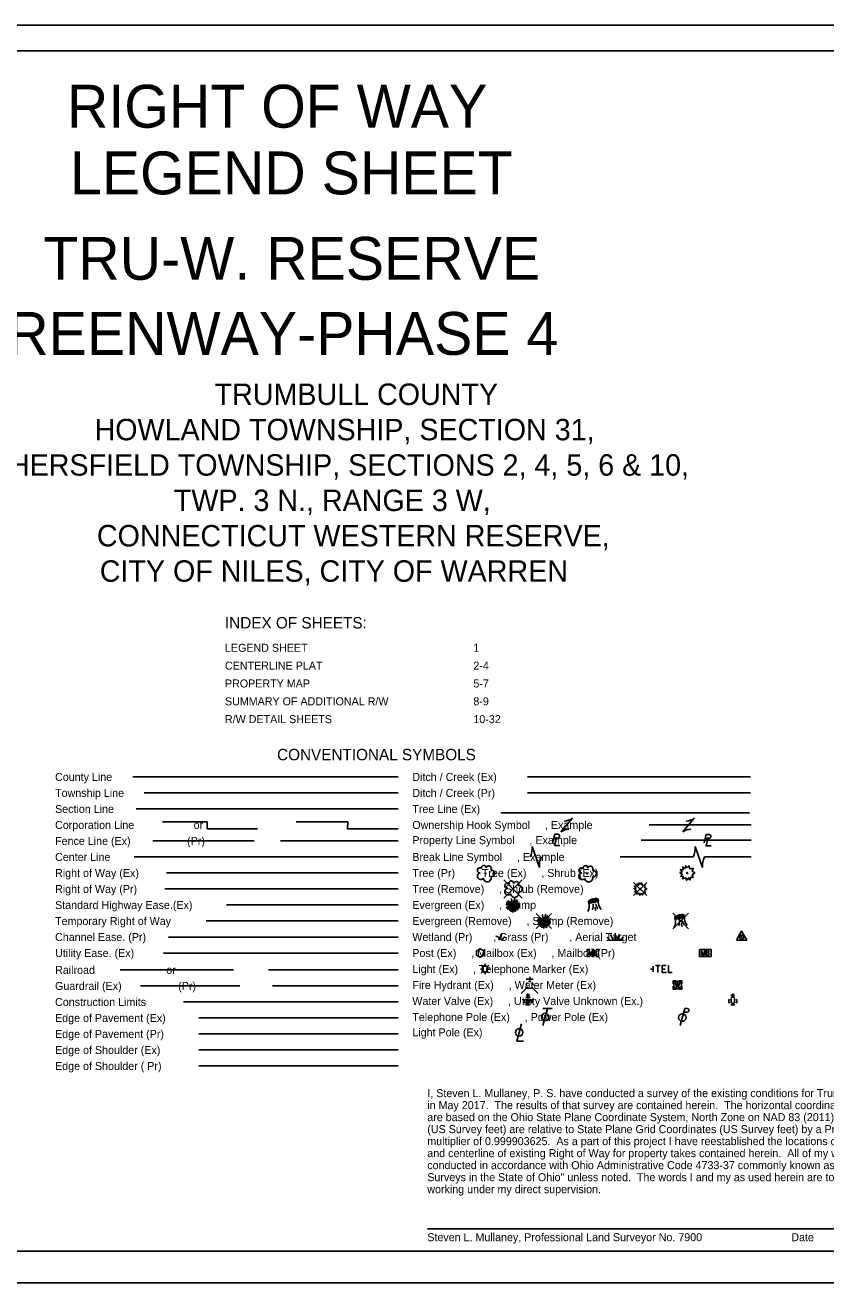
# Model space of a CAD drawing. Extents: x 0 to 34, y -0.1 to 32.4.
# Drawn here: x 11.7 to 25.7, y -0.05 to 21.95 of the extents above; entities that cross this region are included whole.
import ezdxf

# ---------------------------------------------------------------- set-up
doc = ezdxf.new("R2010")
doc.units = 0
for name, color, linetype in [('SH_Border', 7, 'Continuous'), ('SH_Data', 7, 'Continuous'), ('TX_P_Misc', 7, 'Continuous')]:
    doc.layers.add(name, color=color, linetype=linetype)

msp = doc.modelspace()

# ---------------------------------------------------------------- linework, layer by layer
at = {"layer": 'SH_Border'}
msp.add_lwpolyline([(0.001, -0.053), (34.001, -0.053), (34.001, 21.947), (0.001, 21.947)], close=True, dxfattribs=at)
at = {"layer": 'SH_Data'}
msp.add_lwpolyline([(2, 21.5), (33.5, 21.5), (33.5, 0.5), (2, 0.5)], close=True, dxfattribs=at)
at = {"layer": 'TX_P_Misc'}
for p, q in [((13.581, 8.797), (18.22, 8.797)), ((20.486, 8.797), (24.386, 8.797)), ((13.779, 8.517), (18.22, 8.517)), ((20.486, 8.517), (24.386, 8.517)), ((13.636, 8.237), (18.22, 8.237)), ((20.018, 8.167), (24.368, 8.167)), ((14.1, 8.013), (14.883, 8.013)), ((14.883, 8.013), (14.883, 7.887)), ((21.07, 7.834), (21.27, 8.074)), ((21.17, 7.954), (21.17, 7.954)), ((22.616, 7.957), (24.398, 7.957)), ((23.202, 7.834), (23.402, 8.074)), ((23.302, 7.954), (23.302, 7.954)), ((14.883, 7.887), (15.764, 7.887)), ((20.946, 7.726), (21.011, 7.726)), ((23.595, 7.722), (23.66, 7.722)), ((13.933, 7.677), (15.706, 7.677)), ((16.163, 7.677), (18.22, 7.677)), ((20.564, 7.581), (20.694, 7.213)), ((20.987, 7.695), (20.987, 7.695)), ((22.475, 7.692), (24.398, 7.692)), ((23.416, 7.581), (23.546, 7.213)), ((23.635, 7.691), (23.635, 7.691)), ((13.601, 7.397), (18.22, 7.397)), ((20.629, 7.397), (20.629, 7.397)), ((22.105, 7.397), (23.381, 7.397)), ((23.481, 7.397), (23.481, 7.397)), ((23.581, 7.397), (24.398, 7.397)), ((14.169, 7.117), (18.22, 7.117)), ((14.141, 6.837), (18.22, 6.837)), ((20.071, 6.997), (20.392, 6.676)), ((20.392, 6.997), (20.071, 6.676)), ((20.232, 6.837), (20.232, 6.837)), ((22.342, 6.953), (22.574, 6.721)), ((22.574, 6.953), (22.342, 6.721)), ((22.458, 6.837), (22.458, 6.837)), ((20.23, 6.557), (20.132, 6.614)), ((20.23, 6.557), (20.142, 6.644)), ((20.23, 6.557), (20.199, 6.672)), ((20.23, 6.557), (20.261, 6.674)), ((20.23, 6.557), (20.296, 6.654)), ((20.23, 6.557), (20.321, 6.627)), ((15.22, 6.557), (18.22, 6.557)), ((20.106, 6.557), (20.23, 6.557)), ((20.23, 6.557), (20.119, 6.586)), ((20.23, 6.557), (20.122, 6.518)), ((20.23, 6.557), (20.13, 6.5)), ((20.23, 6.557), (20.132, 6.482)), ((20.23, 6.557), (20.156, 6.47)), ((20.23, 6.557), (20.172, 6.456)), ((20.23, 6.557), (20.188, 6.448)), ((20.23, 6.557), (20.198, 6.435)), ((20.23, 6.557), (20.216, 6.442)), ((20.23, 6.557), (20.348, 6.597)), ((20.23, 6.557), (20.342, 6.559)), ((20.23, 6.426), (20.23, 6.557)), ((20.23, 6.557), (20.253, 6.441)), ((20.23, 6.557), (20.278, 6.44)), ((20.23, 6.557), (20.293, 6.462)), ((20.23, 6.557), (20.319, 6.469)), ((20.23, 6.557), (20.325, 6.493)), ((20.23, 6.557), (20.341, 6.508)), ((20.23, 6.557), (20.35, 6.533)), ((20.639, 6.41), (20.906, 6.143)), ((20.906, 6.41), (20.639, 6.143)), ((20.772, 6.277), (20.741, 6.392)), ((20.772, 6.277), (20.804, 6.394)), ((21.658, 6.557), (21.658, 6.557)), ((23.026, 6.416), (23.304, 6.138)), ((23.304, 6.416), (23.026, 6.138)), ((14.865, 6.277), (18.22, 6.277)), ((20.649, 6.277), (20.772, 6.277)), ((20.772, 6.277), (20.662, 6.306)), ((20.772, 6.277), (20.665, 6.238)), ((20.772, 6.277), (20.673, 6.22)), ((20.772, 6.277), (20.675, 6.334)), ((20.772, 6.277), (20.675, 6.202)), ((20.772, 6.277), (20.685, 6.364)), ((20.772, 6.277), (20.699, 6.19)), ((20.772, 6.277), (20.714, 6.176)), ((20.772, 6.277), (20.731, 6.168)), ((20.772, 6.277), (20.741, 6.155)), ((20.772, 6.277), (20.759, 6.162)), ((20.772, 6.277), (20.839, 6.374)), ((20.772, 6.277), (20.864, 6.347)), ((20.772, 6.277), (20.891, 6.317)), ((20.772, 6.277), (20.885, 6.279)), ((20.772, 6.146), (20.772, 6.277)), ((20.772, 6.277), (20.795, 6.161)), ((20.772, 6.277), (20.821, 6.16)), ((20.772, 6.277), (20.836, 6.182)), ((20.772, 6.277), (20.862, 6.189)), ((20.772, 6.277), (20.868, 6.213)), ((20.772, 6.277), (20.884, 6.228)), ((20.772, 6.277), (20.893, 6.253)), ((20.772, 6.277), (20.772, 6.277)), ((23.165, 6.277), (23.165, 6.277)), ((23.165, 6.277), (23.165, 6.277)), ((14.202, 5.997), (18.22, 5.997)), ((21.939, 5.936), (21.871, 5.993)), ((21.988, 5.936), (21.935, 6.043)), ((22.018, 5.937), (22.016, 6.062)), ((22.048, 5.937), (22.097, 6.045)), ((22.096, 5.938), (22.163, 5.997)), ((21.604, 5.778), (21.654, 5.778)), ((21.871, 5.935), (22.164, 5.939)), ((14.119, 5.717), (18.22, 5.717)), ((19.696, 5.485), (19.677, 5.504)), ((19.744, 5.501), (19.744, 5.527)), ((19.811, 5.504), (19.792, 5.485)), ((21.604, 5.656), (21.654, 5.656)), ((21.629, 5.717), (21.629, 5.717)), ((23.596, 5.717), (23.596, 5.717)), ((13.358, 5.421), (15.344, 5.421)), ((15.953, 5.421), (18.22, 5.421)), ((19.692, 5.437), (19.665, 5.437)), ((19.696, 5.388), (19.677, 5.37)), ((19.744, 5.437), (19.744, 5.437)), ((19.744, 5.373), (19.744, 5.346)), ((19.811, 5.37), (19.792, 5.388)), ((19.823, 5.437), (19.796, 5.437)), ((20.523, 5.217), (20.523, 5.303)), ((22.685, 5.437), (22.635, 5.437)), ((22.685, 5.387), (22.685, 5.487)), ((13.712, 5.141), (15.455, 5.141)), ((16.024, 5.141), (18.22, 5.141)), ((20.481, 5.114), (20.377, 5.011)), ((20.583, 5.26), (20.463, 5.26)), ((20.523, 5.157), (20.523, 5.157)), ((20.523, 5.157), (20.523, 5.157)), ((20.565, 5.114), (20.669, 5.011)), ((23.11, 5.157), (23.11, 5.157)), ((14.464, 4.861), (18.22, 4.861)), ((20.524, 4.979), (20.46, 4.979)), ((20.492, 4.947), (20.492, 5.01)), ((20.492, 4.877), (20.492, 4.877)), ((24.109, 4.979), (24.045, 4.979)), ((24.05, 4.92), (24.05, 4.851)), ((24.077, 4.947), (24.077, 5.01)), ((24.077, 4.877), (24.077, 4.877)), ((24.104, 4.92), (24.104, 4.851)), ((20.836, 4.747), (20.755, 4.447)), ((20.916, 4.747), (20.756, 4.747)), ((23.237, 4.747), (23.157, 4.447)), ((23.22, 4.683), (23.279, 4.683)), ((23.237, 4.747), (23.279, 4.747)), ((14.736, 4.581), (18.22, 4.581)), ((14.736, 4.301), (18.22, 4.301)), ((14.736, 4.021), (18.22, 4.021)), ((14.736, 3.741), (18.22, 3.741)), ((18.737, 0.89), (29.675, 0.89))]:
    msp.add_line(p, q, dxfattribs=at)
for points in [[(16.436, 8.013), (17.34, 8.013), (17.334, 7.887), (18.22, 7.887)], [(20.925, 7.646), (20.965, 7.795), (21.016, 7.794)], [(21, 7.743), (20.96, 7.595), (21.048, 7.595)], [(23.574, 7.642), (23.613, 7.791), (23.665, 7.791)], [(23.648, 7.739), (23.609, 7.591), (23.696, 7.591)], [(23.275, 7.207), (23.305, 7.244), (23.326, 7.191), (23.381, 7.2), (23.364, 7.15), (23.411, 7.12), (23.368, 7.083), (23.381, 7.038), (23.343, 7.041), (23.327, 6.995), (23.305, 7.03), (23.271, 6.989), (23.25, 7.034), (23.199, 7.012), (23.208, 7.059), (23.168, 7.055), (23.192, 7.094), (23.153, 7.123), (23.19, 7.136), (23.16, 7.176), (23.206, 7.171), (23.205, 7.223), (23.242, 7.194), (23.253, 7.243), (23.275, 7.207)], [(22.454, 6.914), (22.48, 6.945), (22.498, 6.9), (22.544, 6.908), (22.53, 6.865), (22.57, 6.84), (22.534, 6.808), (22.544, 6.77), (22.512, 6.772), (22.498, 6.734), (22.48, 6.763), (22.451, 6.728), (22.433, 6.766), (22.39, 6.748), (22.398, 6.788), (22.363, 6.784), (22.384, 6.818), (22.351, 6.842), (22.382, 6.853), (22.357, 6.887), (22.396, 6.883), (22.395, 6.927), (22.427, 6.903), (22.436, 6.944), (22.454, 6.914)], [(19.591, 5.679), (19.656, 5.642), (19.721, 5.679), (19.721, 5.754), (19.656, 5.792), (19.591, 5.754), (19.591, 5.679)], [(21.529, 5.729), (21.529, 5.778), (21.578, 5.778)], [(21.564, 5.677), (21.564, 5.757), (21.593, 5.677), (21.621, 5.757), (21.621, 5.677)], [(21.68, 5.72), (21.683, 5.723), (21.685, 5.725), (21.687, 5.727), (21.687, 5.729), (21.689, 5.731), (21.689, 5.733), (21.69, 5.737), (21.69, 5.739), (21.69, 5.742), (21.69, 5.746), (21.689, 5.749), (21.687, 5.751), (21.683, 5.754), (21.681, 5.755), (21.68, 5.756), (21.677, 5.757), (21.646, 5.757), (21.646, 5.677), (21.68, 5.677), (21.685, 5.679), (21.689, 5.683), (21.692, 5.688), (21.694, 5.693), (21.694, 5.699), (21.694, 5.703), (21.693, 5.706), (21.69, 5.712), (21.687, 5.716), (21.68, 5.72), (21.646, 5.72)], [(21.68, 5.778), (21.729, 5.778), (21.729, 5.729)], [(23.531, 5.677), (23.531, 5.757), (23.56, 5.677), (23.588, 5.757), (23.588, 5.677)], [(23.647, 5.72), (23.65, 5.723), (23.652, 5.725), (23.654, 5.727), (23.654, 5.729), (23.655, 5.731), (23.656, 5.733), (23.657, 5.737), (23.657, 5.739), (23.657, 5.742), (23.657, 5.746), (23.655, 5.749), (23.654, 5.751), (23.65, 5.754), (23.648, 5.755), (23.647, 5.756), (23.644, 5.757), (23.613, 5.757), (23.613, 5.677), (23.647, 5.677), (23.652, 5.679), (23.655, 5.683), (23.659, 5.688), (23.661, 5.693), (23.661, 5.699), (23.661, 5.703), (23.66, 5.706), (23.657, 5.712), (23.654, 5.716), (23.647, 5.72), (23.613, 5.72)], [(21.578, 5.656), (21.529, 5.656), (21.529, 5.704)], [(21.729, 5.704), (21.729, 5.656), (21.68, 5.656)], [(22.726, 5.499), (22.804, 5.499)], [(22.765, 5.499), (22.765, 5.374)], [(22.911, 5.499), (22.843, 5.499), (22.843, 5.374), (22.916, 5.374)], [(22.843, 5.437), (22.891, 5.437)], [(22.95, 5.499), (22.95, 5.374), (23.018, 5.374)], [(23.09, 5.232), (23.035, 5.232), (23.035, 5.177)], [(23.035, 5.137), (23.035, 5.082), (23.09, 5.082)], [(23.077, 5.202), (23.094, 5.112), (23.11, 5.202), (23.127, 5.112), (23.144, 5.202)], [(23.185, 5.177), (23.185, 5.232), (23.13, 5.232)], [(23.13, 5.082), (23.185, 5.082), (23.185, 5.137)], [(20.46, 4.918), (20.476, 4.832), (20.492, 4.918), (20.508, 4.832), (20.524, 4.918)], [(20.378, 4.476), (20.299, 4.176), (20.417, 4.176)]]:
    msp.add_lwpolyline(points, dxfattribs=at)
for points in [[(24.141, 5.939), (24.321, 5.939), (24.231, 6.1)], [(23.496, 5.778), (23.696, 5.778), (23.696, 5.656), (23.496, 5.656)], [(19.711, 5.387), (19.777, 5.387), (19.777, 5.487), (19.711, 5.487)]]:
    msp.add_lwpolyline(points, close=True, dxfattribs=at)
for centre, radius in [((19.751, 7.109), 0.0084), ((21.528, 7.105), 0.0072), ((23.279, 7.117), 0.0115), ((20.232, 6.837), 0.0072), ((22.458, 6.837), 0.00979), ((24.231, 5.997), 0.035), ((24.231, 5.997), 0.008), ((23.11, 5.157), 0.0675), ((20.796, 4.597), 0.065), ((23.194, 4.587), 0.065), ((20.338, 4.328), 0.065)]:
    msp.add_circle(centre, radius, dxfattribs=at)
for centre, radius, start, end in [((21.112, 8.289), 0.267, 273.6945, 306.337), ((23.244, 8.289), 0.267, 273.6945, 306.337), ((21.011, 7.76), 0.0345, 270.471, 81.3281), ((21.228, 7.619), 0.267, 93.6945, 126.337), ((23.36, 7.619), 0.267, 93.6945, 126.337), ((23.659, 7.756), 0.0345, 270.471, 81.3281), ((20.232, 7.549), 0.334, 332.9422, 5.5848), ((23.084, 7.548), 0.334, 332.9422, 5.5848), ((21.026, 7.245), 0.334, 152.9422, 185.5848), ((23.878, 7.245), 0.334, 152.9422, 185.5848), ((19.666, 7.062), 0.0592, 96.1722, 320.5737), ((19.652, 7.165), 0.0441, 39.0625, 279.5412), ((19.722, 7.21), 0.0395, 354.0047, 205.9741), ((19.78, 7.031), 0.0685, 184.9476, 19.4572), ((19.806, 7.194), 0.0466, 323.83, 165.0376), ((19.855, 7.11), 0.0574, 259.1453, 101.4596), ((21.443, 7.059), 0.0592, 96.1722, 320.5737), ((21.429, 7.161), 0.0441, 39.0625, 279.5412), ((21.499, 7.206), 0.0395, 354.0047, 205.9741), ((21.557, 7.027), 0.0685, 184.9476, 19.4572), ((21.583, 7.19), 0.0466, 323.83, 165.0376), ((21.632, 7.106), 0.0574, 259.1453, 101.4596), ((20.146, 6.79), 0.0592, 96.1722, 320.5737), ((20.132, 6.893), 0.0441, 39.0625, 279.5412), ((20.202, 6.938), 0.0395, 354.0047, 205.9741), ((20.287, 6.922), 0.0466, 323.83, 165.0376), ((20.336, 6.838), 0.0574, 259.1453, 101.4596), ((20.26, 6.759), 0.0685, 184.9476, 19.4572), ((21.366, 6.54), 0.2, 331.5338, 20.9269), ((21.938, 6.614), 0.215, 171.4106, 219.9194), ((21.382, 6.558), 0.253, 340.7938, 3.5481), ((21.853, 6.517), 0.182, 178.7926, 197.1224), ((21.983, 6.66), 0.316, 194.9653, 212.1216), ((22.874, 6.26), 0.2, 331.5338, 20.9269), ((22.89, 6.278), 0.253, 340.7938, 3.5481), ((23.361, 6.237), 0.182, 178.7926, 197.1224), ((23.491, 6.38), 0.316, 194.9653, 212.1216), ((23.446, 6.334), 0.215, 171.4106, 219.9194), ((20.523, 5.157), 0.06, 140.021, 184.0629), ((20.523, 5.157), 0.06, 211.8788, 255.8479), ((20.523, 5.157), 0.06, 68.1395, 112.038), ((20.523, 5.157), 0.06, 283.8239, 329.9097), ((20.523, 5.157), 0.06, 356.0165, 39.9889), ((20.492, 4.877), 0.07, 150.0184, 209.9816), ((20.492, 4.877), 0.07, 60.0184, 120.0157), ((20.492, 4.877), 0.07, 330.0184, 29.9816), ((24.077, 4.877), 0.07, 150.0184, 209.9816), ((24.077, 4.877), 0.07, 60.0184, 120.0157), ((24.077, 4.864), 0.03, 205.1924, 334.8076), ((24.077, 4.877), 0.07, 330.0184, 29.9816), ((20.492, 4.877), 0.07, 239.9843, 299.9816), ((23.28, 4.715), 0.0319, 268.8767, 91.1233), ((24.077, 4.877), 0.07, 239.9843, 299.9816)]:
    msp.add_arc(centre, radius, start, end, dxfattribs=at)
for centre, major_axis in [((21.639, 6.632), (0.0868, 0.0187)), ((21.639, 6.632), (0.0651, 0.0141)), ((21.639, 6.632), (0.0488, 0.0105)), ((21.639, 6.632), (0.0275, 0.0059)), ((21.639, 6.632), (0.0154, 0.0033)), ((23.147, 6.352), (0.0868, 0.0187)), ((23.147, 6.352), (0.0651, 0.0141)), ((23.147, 6.352), (0.0488, 0.0105)), ((23.147, 6.352), (0.0275, 0.0059)), ((23.147, 6.352), (0.0154, 0.0033))]:
    msp.add_ellipse(centre, major_axis=major_axis, ratio=0.36865, dxfattribs=at)
for points in [[(19.933, 6.012), (19.975, 5.995), (19.992, 5.941)], [(20.021, 5.945), (20.021, 5.993), (20.026, 6.037), (20.035, 6.058)], [(20.048, 5.938), (20.06, 5.977), (20.09, 6)]]:
    msp.add_spline(points, degree=3, dxfattribs=at)

# ---------------------------------------------------------------- texts
for s, height, p in [('RIGHT OF WAY', 0.75, (12.427, 20.154)), ('LEGEND SHEET', 0.75, (12.48, 18.988)), ('TRU-W. RESERVE', 0.75, (12.014, 17.493)), ('GREENWAY-PHASE 4', 0.75, (10.603, 16.18)), ('TRUMBULL COUNTY', 0.375, (15.011, 15.304)), ('HOWLAND TOWNSHIP, SECTION 31,', 0.375, (12.91, 14.686)), ('WEATHERSFIELD TOWNSHIP, SECTIONS 2, 4, 5, 6 & 10,', 0.375, (9.964, 14.067)), ('TWP. 3 N., RANGE 3 W,', 0.375, (14.298, 13.448)), ('CONNECTICUT WESTERN RESERVE,', 0.375, (12.952, 12.829)), ('CITY OF NILES, CITY OF WARREN', 0.375, (13.002, 12.211)), ('INDEX OF SHEETS:', 0.2, (15.192, 11.394)), ('LEGEND SHEET', 0.14, (15.192, 10.986)), ('1', 0.14, (19.538, 10.986)), ('CENTERLINE PLAT', 0.14, (15.192, 10.674)), ('2-4', 0.14, (19.538, 10.674)), ('PROPERTY MAP', 0.14, (15.192, 10.362)), ('5-7', 0.14, (19.538, 10.362)), ('SUMMARY OF ADDITIONAL R/W', 0.14, (15.192, 10.05)), ('8-9', 0.14, (19.538, 10.05)), ('R/W DETAIL SHEETS', 0.14, (15.192, 9.738)), ('10-32', 0.14, (19.538, 9.738)), ('CONVENTIONAL SYMBOLS', 0.2, (16.104, 9.088)), ('County Line', 0.14, (12.22, 8.727)), ('Ditch / Creek (Ex)', 0.14, (18.47, 8.727)), ('Township Line', 0.14, (12.22, 8.447)), ('Ditch / Creek (Pr)', 0.14, (18.47, 8.447)), ('Section Line', 0.14, (12.22, 8.167)), ('Tree Line (Ex)', 0.14, (18.47, 8.167)), ('Corporation Line                    or', 0.14, (12.22, 7.887)), ('Ownership Hook Symbol     , Example', 0.14, (18.47, 7.887)), ('Fence Line (Ex)                   (Pr)', 0.14, (12.22, 7.607)), ('Property Line Symbol     , Example', 0.14, (18.47, 7.622)), ('Center Line', 0.14, (12.22, 7.327)), ('Break Line Symbol     , Example', 0.14, (18.47, 7.327)), ('Right of Way (Ex)', 0.14, (12.22, 7.047)), ('Tree (Pr)       , Tree (Ex)     , Shrub (Ex)', 0.14, (18.47, 7.047)), ('Right of Way (Pr)', 0.14, (12.22, 6.767)), ('Tree (Remove)     , Shrub (Remove)', 0.14, (18.47, 6.767)), ('Standard Highway Ease.(Ex)', 0.14, (12.22, 6.487)), ('Evergreen (Ex)     , Stump ', 0.14, (18.47, 6.487)), ('Temporary Right of Way', 0.14, (12.22, 6.207)), ('Evergreen (Remove)     , Stump (Remove)', 0.14, (18.47, 6.207)), ('Channel Ease. (Pr)', 0.14, (12.22, 5.927)), ('Wetland (Pr)       , Grass (Pr)       , Aerial Target    ', 0.14, (18.47, 5.927)), ('Utility Ease. (Ex)', 0.14, (12.22, 5.647)), ('Post (Ex)     , Mailbox (Ex)     , Mailbox (Pr)', 0.14, (18.47, 5.647)), ('Light (Ex)     , Telephone Marker (Ex)     ', 0.14, (18.47, 5.367)), ('Railroad                        or', 0.14, (12.22, 5.351)), ('Guardrail (Ex)                   (Pr)', 0.14, (12.22, 5.071)), ('Fire Hydrant (Ex)     , Water Meter (Ex)', 0.14, (18.47, 5.087)), ('Construction Limits', 0.14, (12.22, 4.791)), ('Water Valve (Ex)     , Utility Valve Unknown (Ex.)', 0.14, (18.47, 4.807)), ('Edge of Pavement (Ex)', 0.14, (12.22, 4.511)), ('Telephone Pole (Ex)     , Power Pole (Ex)', 0.14, (18.47, 4.527)), ('Light Pole (Ex)     ', 0.14, (18.47, 4.26)), ('Edge of Pavement (Pr)', 0.14, (12.22, 4.231)), ('Edge of Shoulder (Ex)', 0.14, (12.22, 3.951)), ('Edge of Shoulder ( Pr)', 0.14, (12.22, 3.671)), ('I, Steven L. Mullaney, P. S. have conducted a survey of the existing conditions for Trumbull County Metro Parks', 0.14, (18.732, 3.196)), ('in May 2017.  The results of that survey are contained herein.  The horizontal coordinates expressed herein', 0.14, (18.732, 2.986)), ('are based on the Ohio State Plane Coordinate System, North Zone on NAD 83 (2011) datum. The Project Coordinates', 0.14, (18.732, 2.776)), ('(US Survey feet) are relative to State Plane Grid Coordinates (US Survey feet) by a Project Adjustment Factor', 0.14, (18.732, 2.566)), ('multiplier of 0.999903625.  As a part of this project I have reestablished the locations of the existing property lines', 0.14, (18.732, 2.356)), ('and centerline of existing Right of Way for property takes contained herein.  All of my work contained herein was', 0.14, (18.732, 2.146)), ('conducted in accordance with Ohio Administrative Code 4733-37 commonly known as "A Minimum Standards for Boundary', 0.14, (18.732, 1.936)), ('Surveys in the State of Ohio" unless noted.  The words I and my as used herein are to mean either myself or someone', 0.14, (18.732, 1.726)), ('working under my direct supervision.', 0.14, (18.732, 1.516)), ('Steven L. Mullaney, Professional Land Surveyor No. 7900                              Date', 0.14, (18.732, 0.676))]:
    msp.add_text(s, height=height, dxfattribs=at).set_placement(p)

doc.saveas('drawing.dxf')
